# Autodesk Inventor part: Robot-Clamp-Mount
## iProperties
Shininess: 21.0
Length Units: 11269
Angle Units: 11279
Time Units: 11290
Mass Units: 11283
Length Display Precision: 3
Angle Display Precision: 2
Created: 2001-08
Part Number: Robot-Clamp-Mount
Document SubType Name: ﾓﾃﾞﾘﾝｸﾞ
Designer: Administrator
Density: 1 g/cm^3
Density: 0.0
Volumn: 0.0
Area: 0.0
PropertySet Name: Model Information
Control State: 0
Master: False
Checked Out: False
Author: Administrator
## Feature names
1. Extrusion1
2. Extrusion2
3. Extrusion3
4. Extrusion4
5. Extrusion5
